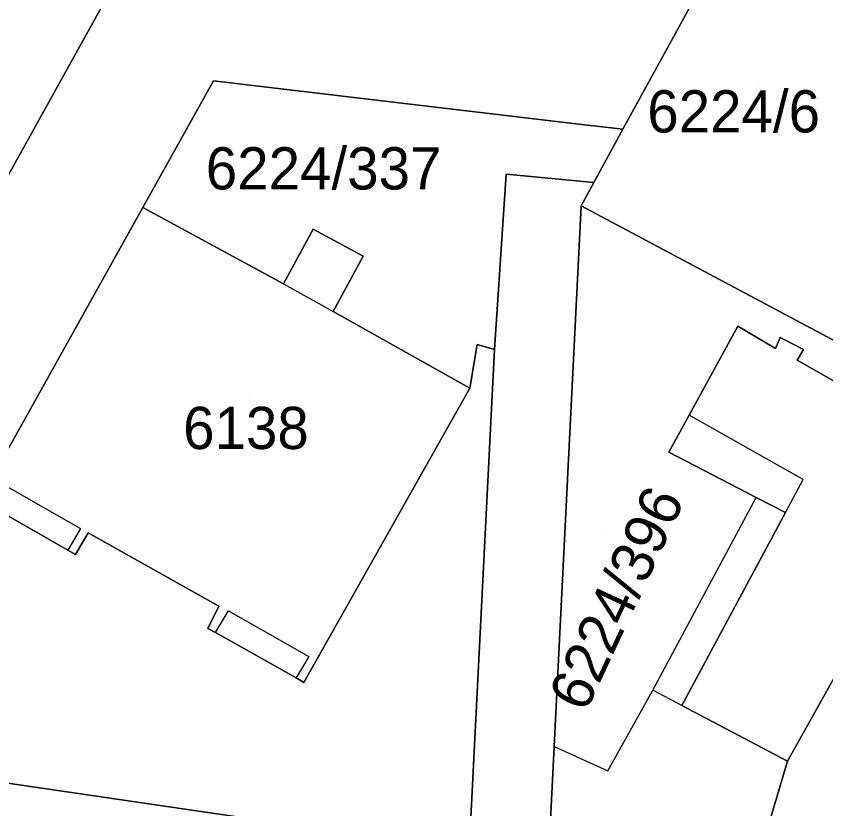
# Model space of a CAD drawing. Extents: x -266199 to -261993, y -1239047 to -1235108.
# Drawn here: x -264005.4 to -263967.07, y -1236465.18 to -1236427.65 of the extents above; entities that cross this region are included whole.
import ezdxf

# ---------------------------------------------------------------- set-up
doc = ezdxf.new("R2010")
doc.units = 0
for name, color, linetype in [('body_kn', 7, 'Continuous'), ('kladpar_druhypozemkov', 7, 'Continuous'), ('kladpar_hranice', 7, 'Continuous'), ('kladpar_parcelnecisla', 7, 'Continuous'), ('kladpar_plochy', 7, 'Continuous'), ('zappar_hrandruhpozemk', 7, 'Continuous')]:
    doc.layers.add(name, color=color, linetype=linetype)

msp = doc.modelspace()

# ---------------------------------------------------------------- linework, layer by layer
at = {"layer": 'body_kn'}
for p, q in [((-263996.06, -1236430.71), (-263996.06, -1236430.71)), ((-263996.06, -1236430.71), (-263996.06, -1236430.71)), ((-263978.77, -1236432.76), (-263978.77, -1236432.76)), ((-263976.68, -1236433.01), (-263976.68, -1236433.01)), ((-263982.2, -1236435.13), (-263982.2, -1236435.13)), ((-263978.06, -1236435.53), (-263978.06, -1236435.53)), ((-263999.4, -1236436.71), (-263999.4, -1236436.71)), ((-263978.66, -1236436.63), (-263978.66, -1236436.63)), ((-263991.34, -1236437.74), (-263991.34, -1236437.74)), ((-263988.98, -1236439.01), (-263988.98, -1236439.01)), ((-263992.74, -1236440.32), (-263992.74, -1236440.32)), ((-263992.74, -1236440.32), (-263992.74, -1236440.32)), ((-263990.4, -1236441.64), (-263990.4, -1236441.64)), ((-263971.23, -1236442.33), (-263971.23, -1236442.33)), ((-263969.23, -1236442.87), (-263969.23, -1236442.87)), ((-263983.57, -1236443.2), (-263983.57, -1236443.2)), ((-263982.75, -1236443.43), (-263982.75, -1236443.43)), ((-263982.75, -1236443.43), (-263982.75, -1236443.43)), ((-263969.45, -1236443.39), (-263969.45, -1236443.39)), ((-263968.13, -1236443.44), (-263968.13, -1236443.44)), ((-263968.43, -1236443.94), (-263968.43, -1236443.94)), ((-263983.93, -1236445.26), (-263983.93, -1236445.26)), ((-263983.93, -1236445.26), (-263983.93, -1236445.26)), ((-263973.54, -1236446.54), (-263973.54, -1236446.54)), ((-263974.5, -1236448.29), (-263974.5, -1236448.29)), ((-263968.14, -1236449.59), (-263968.14, -1236449.59)), ((-263970.36, -1236450.44), (-263970.36, -1236450.44)), ((-263968.98, -1236451.16), (-263968.98, -1236451.16)), ((-263968.98, -1236451.16), (-263968.98, -1236451.16)), ((-264002.35, -1236451.91), (-264002.35, -1236451.91)), ((-264002, -1236452.11), (-264002, -1236452.11)), ((-264002.96, -1236452.94), (-264002.96, -1236452.94)), ((-264002.96, -1236452.94), (-264002.96, -1236452.94)), ((-264002.59, -1236453.14), (-264002.59, -1236453.14)), ((-263995.8, -1236455.59), (-263995.8, -1236455.59)), ((-263995.35, -1236455.81), (-263995.35, -1236455.81)), ((-263996.33, -1236456.64), (-263996.33, -1236456.64)), ((-263995.96, -1236456.84), (-263995.96, -1236456.84)), ((-263991.55, -1236457.97), (-263991.55, -1236457.97)), ((-263992.14, -1236458.98), (-263992.14, -1236458.98)), ((-263992.14, -1236458.98), (-263992.14, -1236458.98)), ((-263991.79, -1236459.2), (-263991.79, -1236459.2)), ((-263975.26, -1236459.57), (-263975.26, -1236459.57)), ((-263975.26, -1236459.57), (-263975.26, -1236459.57)), ((-263973.88, -1236460.3), (-263973.88, -1236460.3)), ((-263973.88, -1236460.3), (-263973.88, -1236460.3)), ((-263979.93, -1236462.23), (-263979.93, -1236462.23)), ((-263979.93, -1236462.23), (-263979.93, -1236462.23)), ((-263968.89, -1236462.93), (-263968.89, -1236462.93)), ((-263977.39, -1236463.38), (-263977.39, -1236463.38))]:
    msp.add_line(p, q, dxfattribs=at)
at = {"layer": 'kladpar_druhypozemkov'}
for p, q in [((-263970.23, -1236430.92), (-263970.23, -1236430.92)), ((-263990.26, -1236433.76), (-263990.26, -1236433.76)), ((-263994.38, -1236445.55), (-263994.38, -1236445.55)), ((-263977.55, -1236451.96), (-263977.55, -1236451.96))]:
    msp.add_line(p, q, dxfattribs=at)
at = {"layer": 'kladpar_hranice'}
for p, q in [((-264006.77, -1236450.76), (-264002.96, -1236452.94)), ((-264002.96, -1236452.94), (-264006.77, -1236450.76)), ((-263995.96, -1236456.84), (-263992.14, -1236458.98)), ((-263992.14, -1236458.98), (-263995.96, -1236456.84))]:
    msp.add_line(p, q, dxfattribs=at)
for points in [[(-263995.95, -1236402.42), (-263991.42, -1236409.29), (-264020.55, -1236461.81), (-264036.84, -1236412.49), (-263997.89, -1236400.02), (-263995.95, -1236402.42)], [(-263982.75, -1236443.43), (-263983.96, -1236467.17), (-264020.55, -1236461.81), (-263991.42, -1236409.29), (-263988.48, -1236408.56), (-263980.16, -1236411.78), (-263968.57, -1236418.22), (-263976.68, -1236433.01), (-263978.77, -1236432.76), (-263996.06, -1236430.71), (-263999.4, -1236436.71), (-264007.13, -1236450.56), (-264006.77, -1236450.76)], [(-263968.57, -1236418.22), (-263959.36, -1236422.88), (-263959.05, -1236423.04), (-263961.99, -1236425.5), (-263964.43, -1236429.74), (-263965.34, -1236431.51), (-263962.76, -1236432.83), (-263959.86, -1236434.31), (-263961.81, -1236437.9), (-263962.14, -1236438.51), (-263964.18, -1236442.27), (-263964.42, -1236442.09), (-263965.62, -1236444.05), (-263966.48, -1236443.5), (-263966.3, -1236443.22), (-263978.66, -1236436.63), (-263978.06, -1236435.53), (-263976.68, -1236433.01), (-263968.57, -1236418.22)], [(-263996.06, -1236430.71), (-263978.77, -1236432.76), (-263976.68, -1236433.01), (-263978.06, -1236435.53), (-263982.2, -1236435.13), (-263982.75, -1236443.43), (-263983.57, -1236443.2), (-263983.93, -1236445.26), (-263990.4, -1236441.64), (-263988.98, -1236439.01), (-263991.34, -1236437.74), (-263992.74, -1236440.32), (-263999.4, -1236436.71), (-263996.06, -1236430.71)], [(-263983.96, -1236467.17), (-263982.75, -1236443.43), (-263982.2, -1236435.13), (-263978.06, -1236435.53), (-263978.66, -1236436.63), (-263979.93, -1236462.23), (-263980.39, -1236471.41)], [(-264006.77, -1236450.76), (-264007.13, -1236450.56), (-263999.4, -1236436.71), (-263992.74, -1236440.32), (-263991.34, -1236437.74), (-263988.98, -1236439.01), (-263990.4, -1236441.64), (-263983.93, -1236445.26)], [(-263966.27, -1236445.18), (-263968.43, -1236443.94), (-263968.13, -1236443.44), (-263969.23, -1236442.87), (-263969.45, -1236443.39), (-263971.23, -1236442.33), (-263973.54, -1236446.54), (-263974.5, -1236448.29), (-263970.36, -1236450.44), (-263968.98, -1236451.16), (-263973.88, -1236460.3), (-263968.89, -1236462.93), (-263972.14, -1236473.87), (-263980.39, -1236471.41), (-263979.93, -1236462.23), (-263978.66, -1236436.63), (-263966.3, -1236443.22), (-263966.48, -1236443.5), (-263965.62, -1236444.05), (-263966.27, -1236445.18)], [(-263951.91, -1236452.89), (-263955.01, -1236458.86), (-263959.15, -1236456.71), (-263963.98, -1236454.15), (-263968.89, -1236462.93), (-263973.88, -1236460.3), (-263968.98, -1236451.16), (-263970.36, -1236450.44), (-263974.5, -1236448.29), (-263973.54, -1236446.54), (-263971.23, -1236442.33), (-263969.45, -1236443.39), (-263969.23, -1236442.87), (-263968.13, -1236443.44), (-263968.43, -1236443.94), (-263966.27, -1236445.18), (-263965.88, -1236445.4), (-263960.69, -1236448.15), (-263955.36, -1236451.03), (-263952.77, -1236452.43), (-263951.91, -1236452.89)], [(-263992.14, -1236458.98), (-263991.79, -1236459.2), (-263983.93, -1236445.26), (-263983.57, -1236443.2), (-263982.75, -1236443.43)], [(-263983.93, -1236445.26), (-263991.79, -1236459.2), (-263992.14, -1236458.98)], [(-264002.96, -1236452.94), (-264002.59, -1236453.14), (-264002, -1236452.11), (-263995.8, -1236455.59), (-263996.33, -1236456.64), (-263995.96, -1236456.84)], [(-263995.96, -1236456.84), (-263996.33, -1236456.64), (-263995.8, -1236455.59), (-264002, -1236452.11), (-264002.59, -1236453.14), (-264002.96, -1236452.94)], [(-263955.01, -1236458.86), (-263951.61, -1236460.9), (-263960.53, -1236477.32), (-263972.14, -1236473.87), (-263968.89, -1236462.93), (-263963.98, -1236454.15), (-263959.15, -1236456.71), (-263955.01, -1236458.86)], [(-263992.48, -1236496.07), (-263992.06, -1236496.12), (-263989.31, -1236479.83), (-263988.27, -1236477.43), (-263986.42, -1236476.94), (-263984.98, -1236477.86), (-263984.53, -1236479.8), (-263985.39, -1236503.87), (-264012.23, -1236499.64), (-264018.9, -1236496.7), (-264016.4, -1236490.65), (-264019.5, -1236474.9), (-264019.9, -1236468.3), (-264020.9, -1236464.1), (-264022.05, -1236461.88), (-264020.55, -1236461.81), (-263983.96, -1236467.17)]]:
    msp.add_lwpolyline(points, dxfattribs=at)
at = {"layer": 'kladpar_plochy'}
msp.add_line((-263991.42, -1236409.29), (-264020.55, -1236461.81), dxfattribs=at)
for points in [[(-263982.75, -1236443.43), (-263983.96, -1236467.17), (-264020.55, -1236461.81), (-263991.42, -1236409.29), (-263988.48, -1236408.56), (-263980.16, -1236411.78), (-263968.57, -1236418.22), (-263976.68, -1236433.01), (-263978.77, -1236432.76), (-263996.06, -1236430.71), (-263999.4, -1236436.71), (-264007.13, -1236450.56), (-264006.77, -1236450.76), (-264002.96, -1236452.94), (-264002.59, -1236453.14), (-264002, -1236452.11), (-263995.8, -1236455.59), (-263996.33, -1236456.64), (-263995.96, -1236456.84), (-263992.14, -1236458.98), (-263991.79, -1236459.2), (-263983.93, -1236445.26), (-263983.57, -1236443.2)], [(-263968.57, -1236418.22), (-263959.36, -1236422.88), (-263959.05, -1236423.04), (-263961.99, -1236425.5), (-263964.43, -1236429.74), (-263965.34, -1236431.51), (-263962.76, -1236432.83), (-263959.86, -1236434.31), (-263961.81, -1236437.9), (-263962.14, -1236438.51), (-263964.18, -1236442.27), (-263964.42, -1236442.09), (-263965.62, -1236444.05), (-263966.48, -1236443.5), (-263966.3, -1236443.22), (-263978.66, -1236436.63), (-263978.06, -1236435.53), (-263976.68, -1236433.01)], [(-263996.06, -1236430.71), (-263978.77, -1236432.76), (-263976.68, -1236433.01), (-263978.06, -1236435.53), (-263982.2, -1236435.13), (-263982.75, -1236443.43), (-263983.57, -1236443.2), (-263983.93, -1236445.26), (-263990.4, -1236441.64), (-263988.98, -1236439.01), (-263991.34, -1236437.74), (-263992.74, -1236440.32), (-263999.4, -1236436.71)], [(-263983.93, -1236445.26), (-263991.79, -1236459.2), (-263992.14, -1236458.98), (-263995.96, -1236456.84), (-263996.33, -1236456.64), (-263995.8, -1236455.59), (-264002, -1236452.11), (-264002.59, -1236453.14), (-264002.96, -1236452.94), (-264006.77, -1236450.76), (-264007.13, -1236450.56), (-263999.4, -1236436.71), (-263992.74, -1236440.32), (-263991.34, -1236437.74), (-263988.98, -1236439.01), (-263990.4, -1236441.64)], [(-263966.27, -1236445.18), (-263968.43, -1236443.94), (-263968.13, -1236443.44), (-263969.23, -1236442.87), (-263969.45, -1236443.39), (-263971.23, -1236442.33), (-263973.54, -1236446.54), (-263974.5, -1236448.29), (-263970.36, -1236450.44), (-263968.98, -1236451.16), (-263973.88, -1236460.3), (-263968.89, -1236462.93), (-263972.14, -1236473.87), (-263980.39, -1236471.41), (-263979.93, -1236462.23), (-263978.66, -1236436.63), (-263966.3, -1236443.22), (-263966.48, -1236443.5), (-263965.62, -1236444.05)], [(-263951.91, -1236452.89), (-263955.01, -1236458.86), (-263959.15, -1236456.71), (-263963.98, -1236454.15), (-263968.89, -1236462.93), (-263973.88, -1236460.3), (-263968.98, -1236451.16), (-263970.36, -1236450.44), (-263974.5, -1236448.29), (-263973.54, -1236446.54), (-263971.23, -1236442.33), (-263969.45, -1236443.39), (-263969.23, -1236442.87), (-263968.13, -1236443.44), (-263968.43, -1236443.94), (-263966.27, -1236445.18), (-263965.88, -1236445.4), (-263960.69, -1236448.15), (-263955.36, -1236451.03), (-263952.77, -1236452.43)], [(-263955.01, -1236458.86), (-263951.61, -1236460.9), (-263960.53, -1236477.32), (-263972.14, -1236473.87), (-263968.89, -1236462.93), (-263963.98, -1236454.15), (-263959.15, -1236456.71)]]:
    msp.add_lwpolyline(points, close=True, dxfattribs=at)
for points in [[(-263983.96, -1236467.17), (-263982.75, -1236443.43), (-263982.2, -1236435.13), (-263978.06, -1236435.53), (-263978.66, -1236436.63), (-263979.93, -1236462.23), (-263980.39, -1236471.41)], [(-264019.9, -1236468.3), (-264020.9, -1236464.1), (-264022.05, -1236461.88), (-264020.55, -1236461.81), (-263983.96, -1236467.17)]]:
    msp.add_lwpolyline(points, dxfattribs=at)
at = {"layer": 'zappar_hrandruhpozemk'}
for p, q in [((-263992.74, -1236440.32), (-263990.4, -1236441.64)), ((-263968.14, -1236449.59), (-263973.54, -1236446.54)), ((-263968.98, -1236451.16), (-263968.14, -1236449.59)), ((-264006.14, -1236449.75), (-264002.35, -1236451.91)), ((-263975.26, -1236459.57), (-263970.36, -1236450.44)), ((-264002.35, -1236451.91), (-264002.96, -1236452.94)), ((-263995.96, -1236456.84), (-263995.35, -1236455.81)), ((-263995.35, -1236455.81), (-263991.55, -1236457.97)), ((-263991.55, -1236457.97), (-263992.14, -1236458.98)), ((-263977.39, -1236463.38), (-263975.26, -1236459.57)), ((-263973.88, -1236460.3), (-263975.26, -1236459.57)), ((-263979.93, -1236462.23), (-263977.39, -1236463.38))]:
    msp.add_line(p, q, dxfattribs=at)

# ---------------------------------------------------------------- texts
at = {"layer": 'kladpar_parcelnecisla'}
for s, p in [('6224/6', (-263975.523, -1236433.16)), ('6224/337', (-263996.423, -1236435.86)), ('6138', (-263997.497, -1236448.15))]:
    msp.add_text(s, height=2, dxfattribs=at).set_placement(p)
msp.add_text('6224/396', height=2, rotation=65, dxfattribs=at).set_placement((-263978.445, -1236460.678))

doc.saveas('drawing.dxf')
